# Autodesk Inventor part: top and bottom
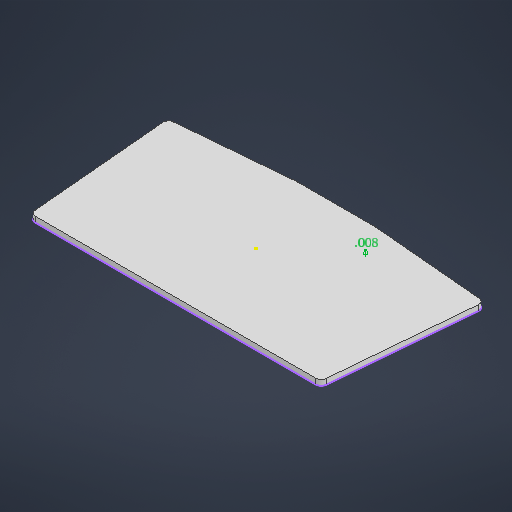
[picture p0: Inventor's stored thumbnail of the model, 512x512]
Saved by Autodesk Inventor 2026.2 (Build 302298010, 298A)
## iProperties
Created: 2026-08
Part Number: top and bottom
Material: Generic
Document SubType Name: Modeling
Designer: cpEwe
Density: 1 g/cm^3
Appearance: Default
Author: cpEwe
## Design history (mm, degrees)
sketch "Sketch1"
  geometry: L1 (21.35, -26.722)-(21.35, 32.611); L2 (34.05, 45.311)-(69.295, 45.311); L3 (75.297, -35.809)-(35.174, -39.372); L4 (21.489, -45.582)-(87.107, -39.841); L5 (81.946, 33.718)-(86.826, -22.052); L6 (89.993, -36.401)-(82.931, 44.318); L7 (19.364, 45.311)-(19.364, -43.689); L8 (-21.555, 45.311)-(19.364, 45.311); L9 (79.768, 47.216)-(-81.959, 47.216); L10 (19.364, -43.689)-(-21.555, -43.689); L11 (-23.403, -45.594)-(21.212, -45.594); L12 (-89.298, -39.841)-(-23.679, -45.582); L13 (-21.555, -43.689)-(-21.555, 45.311); L14 (-23.541, 32.611)-(-23.541, -26.722); L15 (-71.486, 45.311)-(-36.241, 45.311); L16 (-89.016, -22.052)-(-84.137, 33.718); L17 (-85.122, 44.318)-(-92.184, -36.401); L18 (-37.365, -39.372)-(-77.488, -35.809); L19 (-23.741, -26.722)-(-23.741, 32.611); L20 (-36.241, 45.111)-(-71.486, 45.111); L21 (-83.938, 33.701)-(-88.817, -22.07); L22 (-77.471, -35.61)-(-37.347, -39.173); A1 r 12.7 centre (34.05, -26.722) between (21.35, -26.722) and (35.174, -39.372); A2 r 12.7 centre (74.174, -23.159) between (75.297, -35.809) and (86.826, -22.052); A3 r 12.7 centre (69.295, 32.611) between (81.946, 33.718) and (69.295, 45.311); A4 r 3.175 centre (79.768, 44.041) between (82.931, 44.318) and (79.768, 47.216); A5 r 12.7 centre (34.05, 32.611) between (34.05, 45.311) and (21.35, 32.611); A6 r 3.175 centre (86.83, -36.678) between (87.107, -39.841) and (89.993, -36.401); A7 r 3.175 centre (21.212, -42.419) between (21.212, -45.594) and (21.489, -45.582); A8 r 3.175 centre (-23.403, -42.419) between (-23.679, -45.582) and (-23.403, -45.594); A9 r 12.7 centre (-36.241, 32.611) between (-23.541, 32.611) and (-36.241, 45.311); A10 r 12.7 centre (-36.241, -26.722) between (-37.365, -39.372) and (-23.541, -26.722); A11 r 12.7 centre (-76.365, -23.159) between (-89.016, -22.052) and (-77.488, -35.809); A12 r 12.7 centre (-71.486, 32.611) between (-71.486, 45.311) and (-84.137, 33.718); A13 r 3.175 centre (-81.959, 44.041) between (-81.959, 47.216) and (-85.122, 44.318); A14 r 3.175 centre (-89.021, -36.678) between (-92.184, -36.401) and (-89.298, -39.841); A15 r 12.5 centre (-36.241, 32.611) between (-23.741, 32.611) and (-36.241, 45.111); A16 r 12.5 centre (-71.486, 32.611) between (-71.486, 45.111) and (-83.938, 33.701); A17 r 12.5 centre (-76.365, -23.159) between (-88.817, -22.07) and (-77.471, -35.61); A18 r 12.5 centre (-36.241, -26.722) between (-37.347, -39.173) and (-23.741, -26.722); 2 further points
  constraints: 44 end point, 36 point on circle, 18 centre point, 7 other
  dimensions: "d4" = 0.2 radial gap between concentric circles of A10 A18
extrude "Extrusion1" new body sketch "Sketch1" distance "d0" = 3.175; taper "d1" = 0 deg
sketch "Sketch2"
  geometry: 1 further point
extrude "Extrusion2" join sketch "Sketch1" distance "d2" = 2; taper "d3" = 0 deg
body "Solid1"
